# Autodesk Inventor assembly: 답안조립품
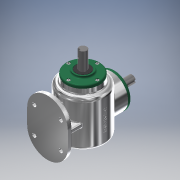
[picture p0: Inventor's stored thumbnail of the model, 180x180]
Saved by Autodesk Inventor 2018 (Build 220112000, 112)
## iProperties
Created: 2023-01
Part Number: 답안조립품
Material: 일반
Document SubType Name: Assembly
Designer: home
Author: home
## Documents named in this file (14)
- C:\Users\home\Desktop\730106V1008\답안조립품.iam
- C:\Users\home\Desktop\730106V1008\본체.ipt
- C:\Users\home\Desktop\730106V1008\M4.ipt
- C:\Users\home\Desktop\730106V1008\메인 베벨기어.ipt
- C:\Users\home\Desktop\730106V1008\메인 축.ipt
- 메인 축.ipt
- C:\Users\home\Desktop\730106V1008\베어링 6203.ipt
- C:\Users\home\Desktop\730106V1008\서브 베벨기어.ipt
- C:\Users\home\Desktop\730106V1008\서브 축.ipt
- 서브 축.ipt
- C:\Users\home\Desktop\730106V1008\오일실 17 32 8.ipt
- C:\Users\home\Desktop\730106V1008\커버.ipt
- C:\Users\home\Desktop\730106V1008\키 5x5.ipt
- C:\Users\home\Desktop\730106V1008\키 4x4.ipt
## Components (8 placed, 1 different names)
1. M4:1
2. M4:3
3. M4:4
4. M4:5
5. M4:2
6. M4:6
7. M4:7
8. M4:8
